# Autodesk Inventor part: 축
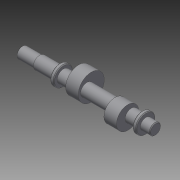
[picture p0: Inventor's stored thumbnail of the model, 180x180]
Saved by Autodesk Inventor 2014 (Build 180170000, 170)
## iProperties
Created: 2014-12
Part Number: 축
Material: 일반
Document SubType Name: Modeling
Designer: Owner
Density: 1 g/cm^3
Appearance: 기본값
Author: Owner
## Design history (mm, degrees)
sketch "스케치1"
  geometry: L1 (-90, 0)-(90, 0); L2 (-90, 0)-(-90, 7.5); L3 (-90, 7.5)-(-66, 7.5); L4 (-66, 7.5)-(-66, 8.5); L5 (-66, 8.5)-(-39, 8.5); L6 (-39, 8.5)-(-39, 13); L7 (-39, 13)-(-34, 13); L8 (-34, 13)-(-34, 8.5); L9 (-34, 8.5)-(72, 8.5); L10 (72, 8.5)-(72, 13); L11 (72, 13)-(77, 13); L12 (77, 13)-(77, 7.5); L13 (77, 7.5)-(90, 7.5); L14 (90, 7.5)-(90, 0); 2 further points
  constraints: 28 end point, 10 parallel, 2 horizontal alignment, 2 perpendicular, 1 coincident, 1 collinear, 1 horizontal, 1 midpoint
  dimensions: "d0" = 180 distance of L1.start L1.end; "d1" = 15 diameter of L3 L1; "d2" = 17 diameter of L5 L1; "d3" = 26 diameter of L7 L1; "d4" = 17 diameter of L9 L1; "d5" = 15 diameter of L13 L1; "d6" = 5 distance of L10.end L11.end; "d7" = 26 diameter of L11 L1; "d8" = 5 distance between parallel lines of L8 L6; "d9" = 24 distance of L2.end L3.end; "d10" = 27 distance of L4.end L5.end; "d11" = 13 distance of L12.end L13.end
revolve "회전1" sketch "스케치1" stored, may be unused: angle "d12" = 90 deg
node "작업 평면1"
sketch "스케치2"
  geometry: C1 r 17.5 at (0, 6); 1 further point
  constraints: 1 centre point, 1 vertical alignment
  dimensions: "d14" = 35 diameter of C1; "d15" = 6 distance of C1.centre point (0, 0)
extrude "돌출1" join sketch "스케치2" distance "d16" = 17; taper "d17" = 0 deg
node "작업 평면2"
sketch "스케치3"
  geometry: C1 r 15 at (0, -5); 1 further point
  constraints: 1 centre point, 1 vertical alignment
  dimensions: "d19" = 30 diameter of C1; "d20" = 5 distance of C1.centre point (0, 0)
extrude "돌출2" join sketch "스케치3" distance "d21" = 17; taper "d22" = 0 deg
node "작업 평면3"
sketch "스케치4"
  geometry: L1 (29.5, 0)-(-5.5, 0); L2 (12, 2.5)-(-5.5, 2.5); L3 (-5.5, -2.5)-(12, -2.5); L4 (12, 7.5)-(12, -7.5) reference; L5 (-12, 7.5)-(-12, -7.5) reference; A1 r 2.5 centre (-5.5, 0) between (-5.5, 2.5) and (-5.5, -2.5); 3 further points
  constraints: 8 end point, 2 midpoint, 2 point on circle, 2 point on line, 2 tangent, 1 centre point, 1 coincident, 1 horizontal, 1 parallel
  dimensions: "d23" = 5 distance between parallel lines of L2 L3; "d24" = 20 dimension on A1 L4
extrude "돌출3" cut sketch "스케치4" distance "d25" = 3; taper "d26" = 0 deg
chamfer "모따기1" distance "d27" = 1; stored, may be unused: second distance "d28" = 2, angle "d29" = 45 deg
node "솔리드1"
node "투영된 루프1"
other parameters: "d13" = -70.5, "d18" = -32.5
